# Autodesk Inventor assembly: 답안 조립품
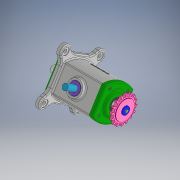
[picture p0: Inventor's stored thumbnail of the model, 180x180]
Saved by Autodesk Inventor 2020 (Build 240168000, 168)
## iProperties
Created: 2022-01
Part Number: 답안 조립품
Document SubType Name: Assembly
Designer: user
Author: user
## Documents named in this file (13)
- C:\Users\user\Desktop\720117V1008\답안 조립품.iam
- C:\Users\user\Desktop\720117V1008\베어링 6203.ipt
- C:\Users\user\Desktop\720117V1008\본체.ipt
- C:\Users\user\Desktop\720117V1008\볼트 M4 x 12.ipt
- C:\Users\user\Desktop\720117V1008\부시.ipt
- C:\Users\user\Desktop\720117V1008\스프로킷.ipt
- C:\Users\user\Desktop\720117V1008\슬라이더.ipt
- C:\Users\user\Desktop\720117V1008\오일 실 17 x 30 x 8.ipt
- C:\Users\user\Desktop\720117V1008\와셔 4 x 20.ipt
- C:\Users\user\Desktop\720117V1008\육각머리볼트 M4.ipt
- C:\Users\user\Desktop\720117V1008\커버.ipt
- C:\Users\user\Desktop\720117V1008\키 5 x 5.ipt
- C:\Users\user\Desktop\720117V1008\편심축.ipt
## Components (8 placed, 1 different names)
1. M4x0.7x12:1
2. M4x0.7x12:2
3. M4x0.7x12:3
4. M4x0.7x12:4
5. M4x0.7x12:5
6. M4x0.7x12:6
7. M4x0.7x12:7
8. M4x0.7x12:8
